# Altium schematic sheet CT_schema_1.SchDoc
size 470 x 429 mm
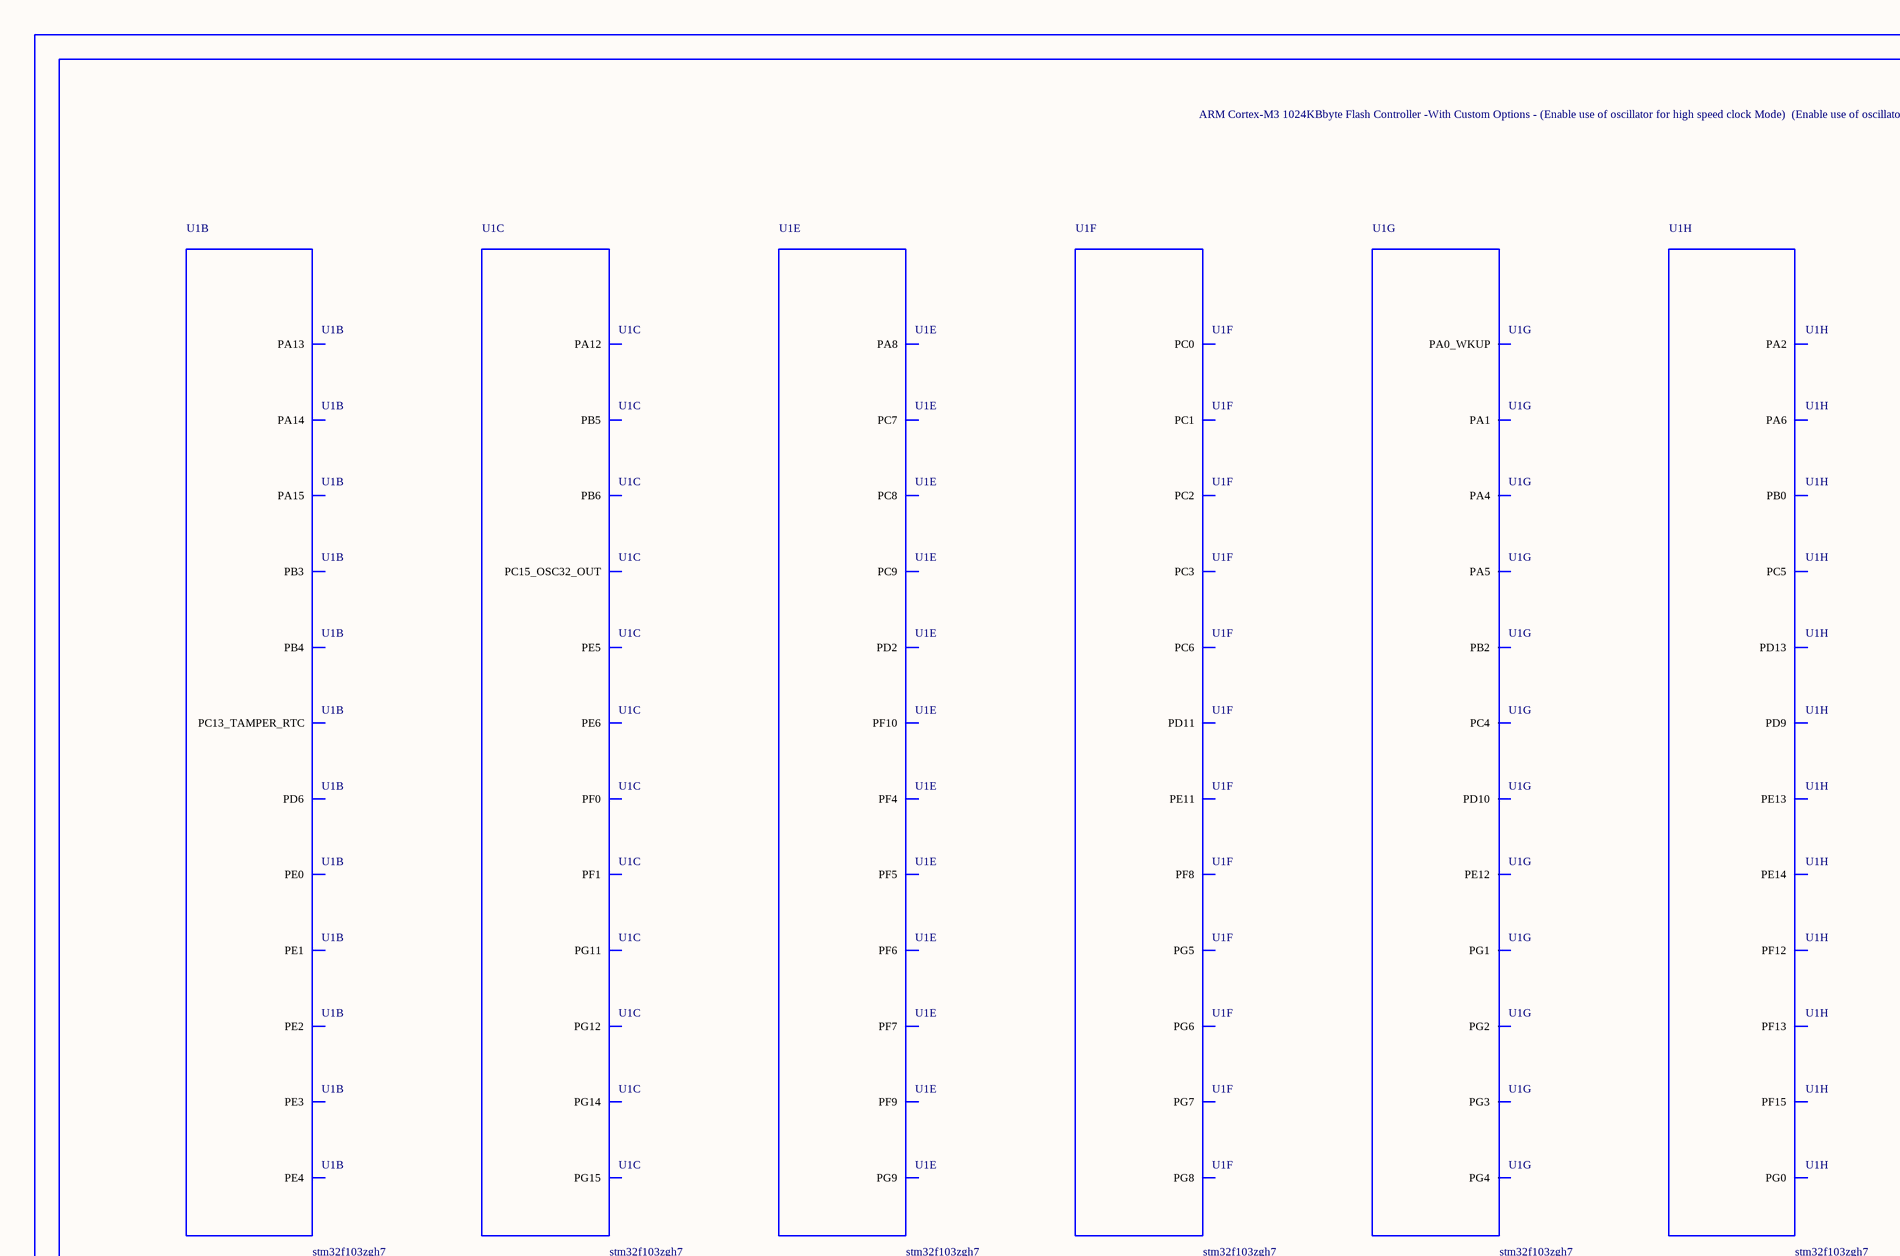
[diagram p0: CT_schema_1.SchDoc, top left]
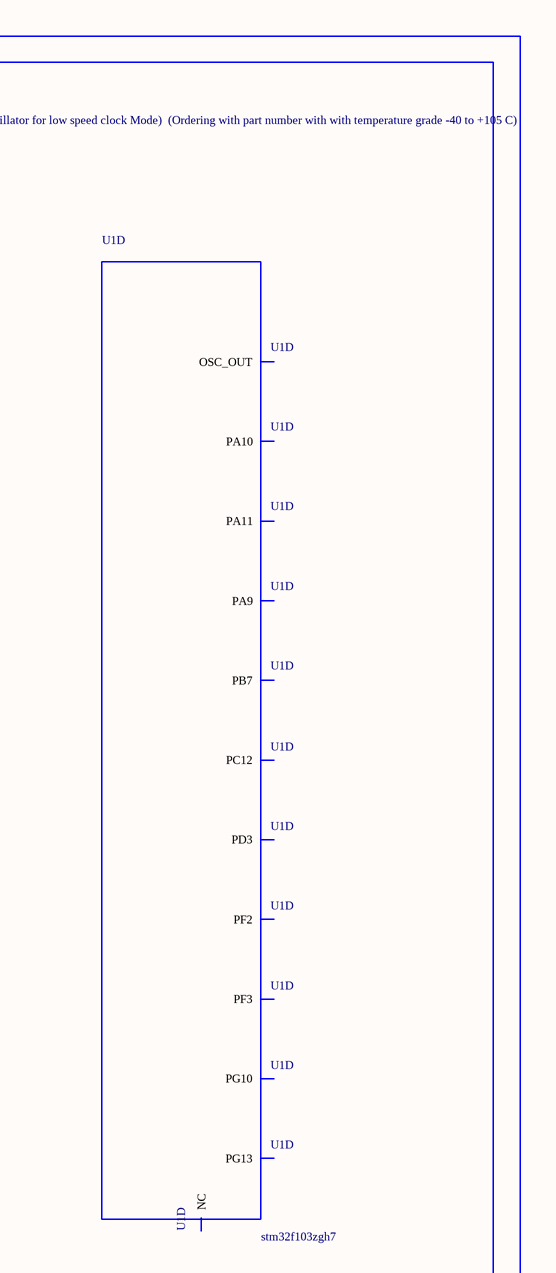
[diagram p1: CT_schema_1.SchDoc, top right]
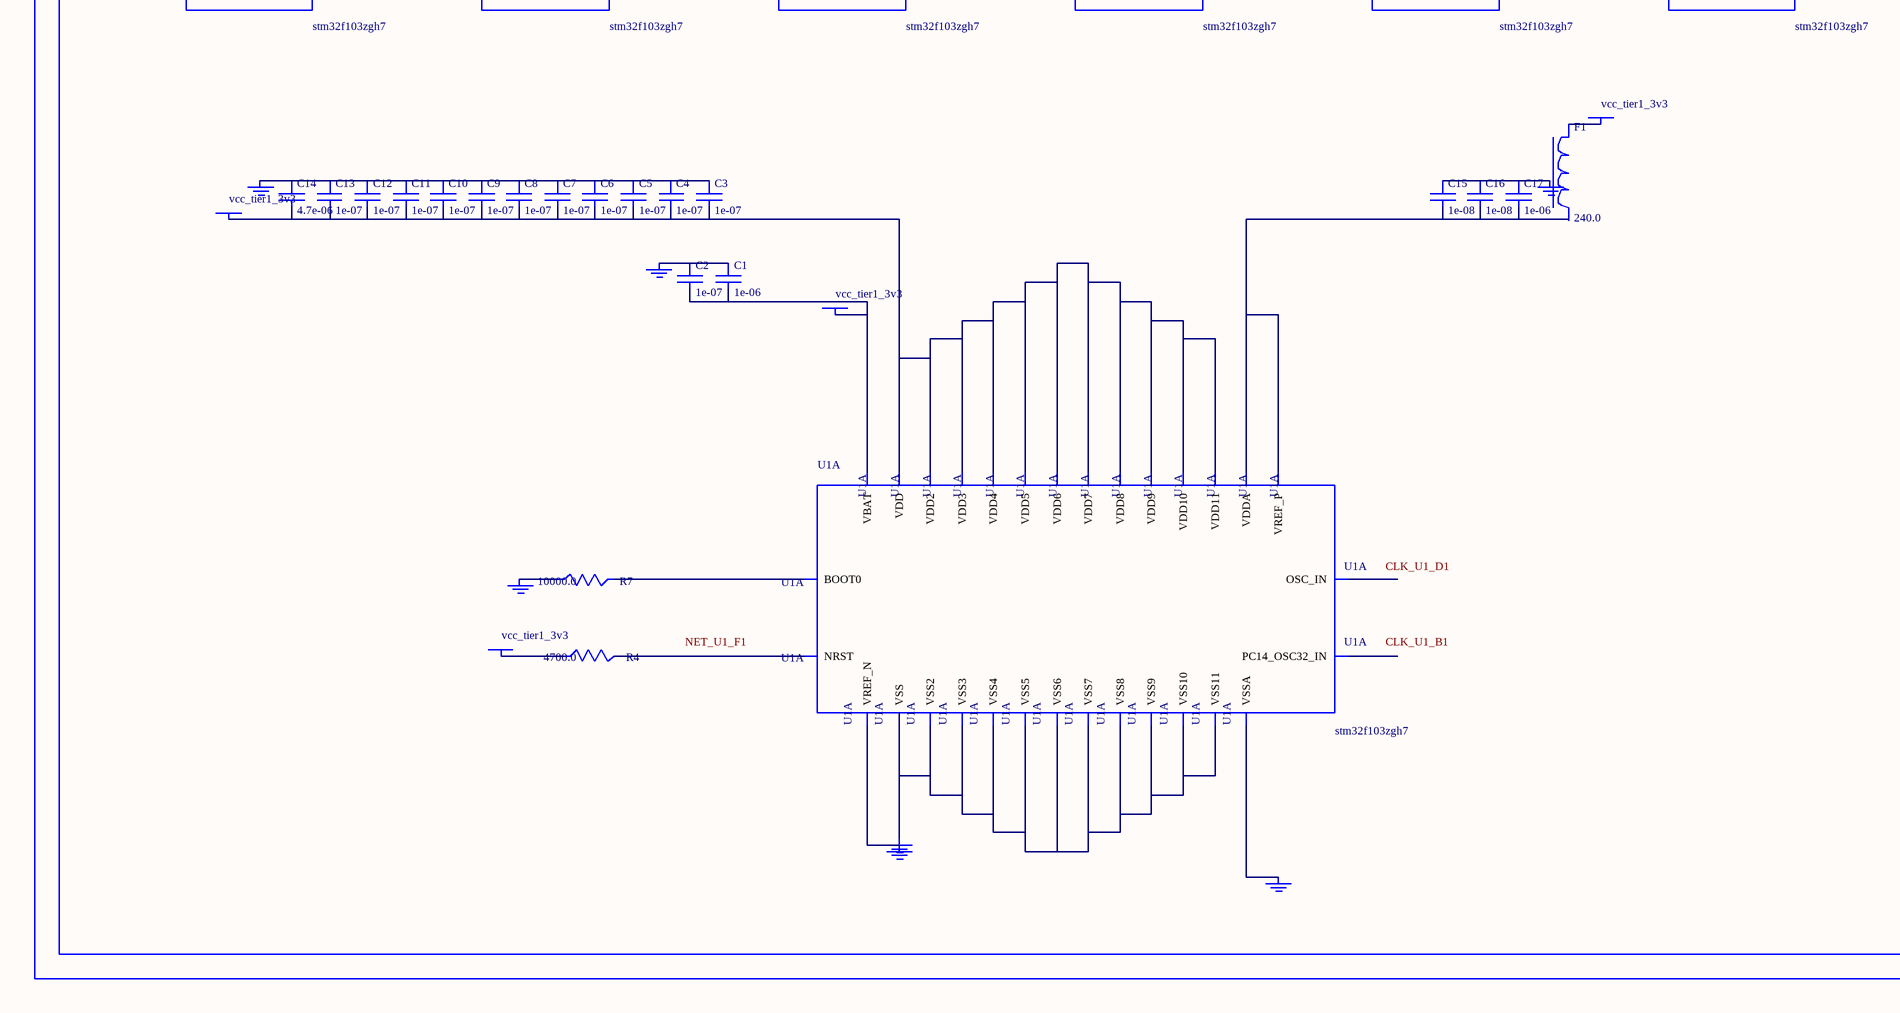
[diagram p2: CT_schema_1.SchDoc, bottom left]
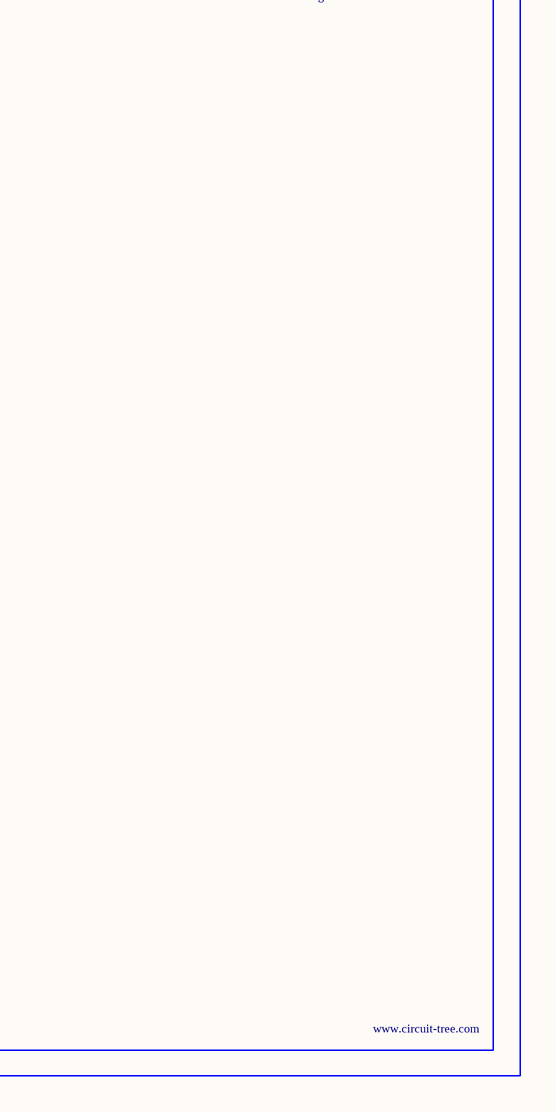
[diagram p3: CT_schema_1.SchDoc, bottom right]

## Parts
BORDER0  (no value)
C1  1e-06  [C0603]
C2  1e-07  [C0603]
C3  1e-07  [C0603]
C4  1e-07  [C0603]
C5  1e-07  [C0603]
C6  1e-07  [C0603]
C7  1e-07  [C0603]
C8  1e-07  [C0603]
C9  1e-07  [C0603]
C10  1e-07  [C0603]
C11  1e-07  [C0603]
C12  1e-07  [C0603]
C13  1e-07  [C0603]
C14  4.7e-06  [C0603]
C15  1e-08  [C0603]
C16  1e-08  [C0603]
C17  1e-06  [C0603]
F1  240.0  [L0603]
GND_INSTANCE_0_0  (no value)
GND_INSTANCE_0_1  (no value)
GND_INSTANCE_0_2  (no value)
GND_INSTANCE_0_3  (no value)
GND_INSTANCE_0_4  (no value)
GND_INSTANCE_0_5  (no value)
GND_INSTANCE_0_6  (no value)
POWER_INSTANCE_0_0  vcc_tier1_3v3
POWER_INSTANCE_0_1  vcc_tier1_3v3
POWER_INSTANCE_0_2  vcc_tier1_3v3
POWER_INSTANCE_0_3  vcc_tier1_3v3
R4  4700.0  [R0603]
R7  10000.0  [R0603]
U1  stm32f103zgh7  [LFBGA144]  (parts A,B,C,D,E,F,G,H of 12)

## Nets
NetC1_1: C1.1 C2.1 GND_INSTANCE_0_0.0(GND)
NetC1_2: C1.2 C2.2 POWER_INSTANCE_0_0.0(PWR) U1.C2(VBAT)
NetC3_1: C3.1 C4.1 C5.1 C6.1 C7.1 C8.1 C9.1 C10.1 C11.1 C12.1 C13.1 C14.1 GND_INSTANCE_0_2.0(GND)
NetC3_2: C3.2 C4.2 C5.2 C6.2 C7.2 C8.2 C9.2 C10.2 C11.2 C12.2 C13.2 C14.2 POWER_INSTANCE_0_2.0(PWR) U1.D3(VDD) U1.F4(VDD3) U1.F5(VDD4) U1.F6(VDD5) U1.F7(VDD6) U1.F8(VDD7) U1.F9(VDD8) U1.F10(VDD2) U1.G5(VDD9) U1.G6(VDD10) U1.G7(VDD11)
NetC15_1: C15.1 C16.1 C17.1 GND_INSTANCE_0_1.0(GND)
NetC15_2: C15.2 C16.2 C17.2 U1.L1(VREF_P) U1.M1(VDDA)
NetF1_1: F1.1 POWER_INSTANCE_0_1.0(PWR)
NetGND_INSTANCE_0_3_0: GND_INSTANCE_0_3.0(GND) R7.1
NetGND_INSTANCE_0_4_0: GND_INSTANCE_0_4.0(GND) U1.J1(VSSA)
NetGND_INSTANCE_0_5_0: GND_INSTANCE_0_5.0(GND) U1.K1(VREF_N)
NetGND_INSTANCE_0_6_0: GND_INSTANCE_0_6.0(GND) U1.D2(VSS) U1.E5(VSS2) U1.E6(VSS3) U1.E7(VSS4) U1.G4(VSS6) U1.G8(VSS7) U1.G9(VSS8) U1.G10(VSS5) U1.H5(VSS9) U1.H6(VSS10) U1.H7(VSS11)
NetPOWER_INSTANCE_0_3_0: POWER_INSTANCE_0_3.0(PWR) R4.1
NetR4_2: R4.2 U1.F1(NRST)
NetR7_2: R7.2 U1.D5(BOOT0)

Not connected (* = marked no-connect by the designer): F1 2; U1 A1(PC13_TAMPER_RTC) A2(PE3) A3(PE2) A4(PE1) A5(PE0) A6(PB4) A7(PB3) A8(PD6) A10(PA15) A11(PA14) A12(PA13) B1(PC14_OSC32_IN) B2(PE4) B3(PE5) B4(PE6) B6(PB5) B7(PG15) B8(PG12) B12(PA12) C1(PC15_OSC32_OUT) C3(PF0) C4(PF1) C6(PB6) C7(PG14) C8(PG11) C10(PC12) C11(NC) C12(PA11) D1(OSC_IN) D4(PF2) D6(PB7) D7(PG13) D8(PG10) D9(PD3) D11(PA10) D12(PA9) E1(OSC_OUT) E2(PF3) E3(PF4) E4(PF5) E8(PG9) E9(PD2) E11(PC9) E12(PA8) F2(PF7) F3(PF6) F11(PC8) F12(PC7) G1(PF10) G2(PF9) G3(PF8) G11(PG8) G12(PC6) H1(PC0) H2(PC1) H3(PC2) H4(PC3) H8(PE11) H9(PD11) H10(PG7) H11(PG6) H12(PG5) J2(PA0_WKUP) J3(PA4) J4(PC4) J5(PB2) J6(PG1) J8(PE12) J9(PD10) J10(PG4) J11(PG3) J12(PG2) K2(PA1) K3(PA5) K4(PC5) K5(PF13) K6(PG0) K8(PE13) K9(PD9) K10(PD13) L2(PA2) L3(PA6) L4(PB0) L5(PF12) L6(PF15) L8(PE14)

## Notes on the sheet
- Labels drawn without touching a wire or pin: CLK_U1_B1, CLK_U1_D1, NET_U1_F1

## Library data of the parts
BORDER0 = BORDER_PAGE0
C1 C17 = C0603C105K3RACTU
C2-C13 = 06035C104K4Z2A
C14 = GRM188R6YA475KE15D
C15 C16 = 06035C103K4Z2A
F1 = Z0603C241ASMST
GND_INSTANCE_0_0-GND_INSTANCE_0_6 = GND
POWER_INSTANCE_0_0-POWER_INSTANCE_0_3 = PWR
R4 = RC0603JR-074K7L
R7 = RC0603JR-0710KL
